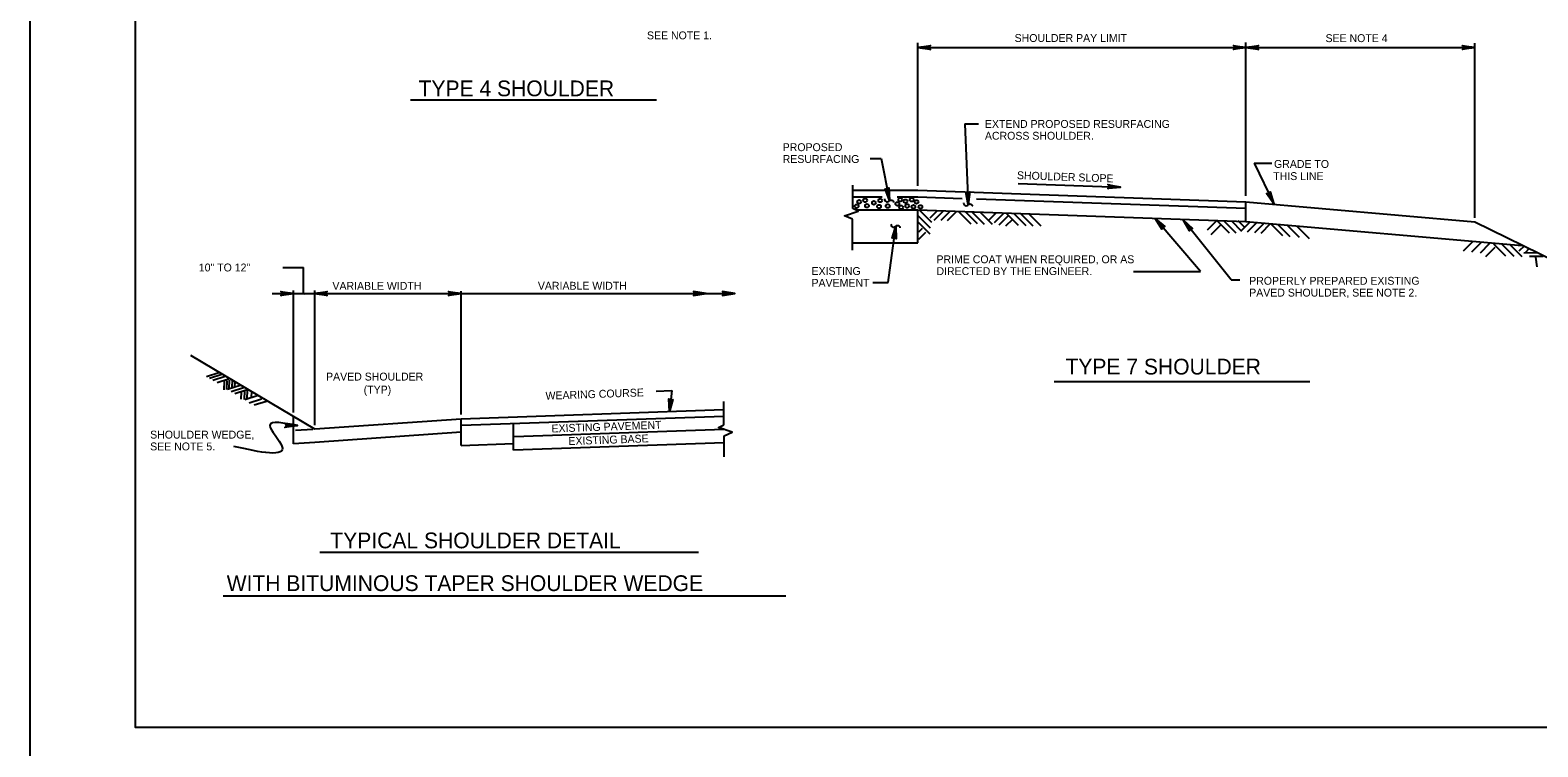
# Model space of a CAD drawing. Extents: x 638216 to 639962, y 297510 to 299292.
# Drawn here: x 638216 to 638790, y 298112 to 298385 of the extents above; entities that cross this region are included whole.
import ezdxf

# ---------------------------------------------------------------- set-up
doc = ezdxf.new("R2010")
doc.units = 0
for name, color, linetype in [('1', 7, 'Continuous'), ('2', 7, 'Continuous'), ('3', 7, 'Continuous'), ('PLT-BNDY', 7, 'Continuous')]:
    doc.layers.add(name, color=color, linetype=linetype)

msp = doc.modelspace()

# ---------------------------------------------------------------- linework, layer by layer
at = {"layer": '1'}
msp.add_lwpolyline([(639041.88, 298119.24), (639041.88, 298683.24), (638255.88, 298683.24), (638255.88, 298119.24), (639041.88, 298119.24), (639041.88, 298145.6), (638841.88, 298145.6), (638841.88, 298210.28), (639041.88, 298210.28), (639041.88, 298239.24), (638841.88, 298239.24), (638841.88, 298119.24), (638920.69, 298119.24), (638920.69, 298145.6), (638920.69, 298119.24), (638997.69, 298119.24), (638997.69, 298145.6), (638997.69, 298133.28), (639041.88, 298133.28)], dxfattribs=at)
msp.add_lwpolyline([(639041.88, 298119.24), (639041.88, 298683.24), (638255.88, 298683.24), (638255.88, 298119.24), (639041.88, 298119.24), (639041.88, 298145.6), (638841.88, 298145.6), (638841.88, 298210.28), (639041.88, 298210.28), (639041.88, 298239.24), (638841.88, 298239.24), (638841.88, 298119.24), (638920.69, 298119.24), (638920.69, 298145.6), (638920.69, 298119.24), (638997.69, 298119.24), (638997.69, 298145.6), (638997.69, 298133.28), (639041.88, 298133.28)], dxfattribs=at)
msp.add_spline([(638317.85, 298234.02), (638307.19, 298234.02), (638311.76, 298226.19), (638293.48, 298226.05)], degree=3, dxfattribs=at)
at = {"layer": '2'}
for p, q in [((638553.97, 298325.26), (638553.97, 298379.73)), ((638678.89, 298321.47), (638678.89, 298379.79)), ((638766.06, 298313.12), (638766.06, 298379.51)), ((638553.97, 298377.9), (638678.88, 298377.9)), ((638678.89, 298377.9), (638766.06, 298377.9)), ((638360.7, 298357.94), (638454.42, 298357.94)), ((638571.85, 298348.86), (638577.04, 298348.86)), ((638571.85, 298348.86), (638573.14, 298318.14)), ((638535.75, 298335.69), (638539.95, 298335.69)), ((638539.95, 298335.69), (638543.08, 298319.63)), ((638681.97, 298333.88), (638688.78, 298333.88)), ((638681.97, 298333.88), (638689.53, 298318.4)), ((638529.16, 298316.67), (638529.16, 298325.51)), ((638529.16, 298323.57), (638553.97, 298323.57)), ((638529.16, 298321.07), (638540.28, 298321.07)), ((638546, 298321.07), (638553.97, 298321.07)), ((638553.97, 298323.57), (638678.89, 298319.21)), ((638553.97, 298321.07), (638570.76, 298320.48)), ((638592.07, 298326.2), (638631.06, 298324.81)), ((638530.31, 298316.07), (638553.97, 298316.07)), ((638553.97, 298303.57), (638553.97, 298316.07)), ((638553.97, 298316.07), (638678.89, 298311.71)), ((638554.61, 298316.03), (638559.18, 298311.47)), ((638561.25, 298315.73), (638558.46, 298312.93)), ((638563.62, 298315.65), (638560.04, 298312.07)), ((638566.23, 298315.67), (638562.66, 298312.09)), ((638568.71, 298315.45), (638565.14, 298311.88)), ((638569.52, 298315.36), (638574.09, 298310.79)), ((638571.94, 298315.44), (638576.51, 298310.87)), ((638574.62, 298315.28), (638579.19, 298310.72)), ((638576.3, 298320.29), (638678.89, 298316.71)), ((638577.71, 298315.21), (638582.27, 298310.64)), ((638678.89, 298311.71), (638678.89, 298319.21)), ((638678.89, 298319.21), (638766.06, 298311.58)), ((638529.1, 298300.83), (638529.1, 298312.52)), ((638542.57, 298288.5), (638545.52, 298309.97)), ((638553.93, 298311.54), (638558.5, 298306.98)), ((638554.01, 298313.89), (638558.57, 298309.33)), ((638583.5, 298314.75), (638580.96, 298312.2)), ((638586.6, 298314.78), (638583.02, 298311.2)), ((638588.37, 298313.82), (638584.79, 298310.24)), ((638589.91, 298312.43), (638587.37, 298309.89)), ((638587.56, 298314.8), (638592.13, 298310.24)), ((638590.49, 298314.7), (638595.06, 298310.14)), ((638593.14, 298314.63), (638597.71, 298310.06)), ((638596.23, 298314.55), (638600.79, 298309.99)), ((638661.57, 298292.68), (638644.34, 298312.86)), ((638673.22, 298289.43), (638654.97, 298312.31)), ((638667.65, 298311.92), (638664.07, 298308.35)), ((638669.06, 298310.13), (638665.49, 298306.55)), ((638667.9, 298311.95), (638672.47, 298307.38)), ((638670.51, 298311.95), (638675.07, 298307.38)), ((638673.59, 298311.7), (638676.96, 298308.32)), ((638675.78, 298312.12), (638678.51, 298309.4)), ((638680.33, 298311.47), (638676.76, 298307.89)), ((638678.89, 298311.71), (638784.07, 298302.5)), ((638682.93, 298311.22), (638679.36, 298307.64)), ((638685.66, 298310.99), (638682.09, 298307.41)), ((638688.14, 298310.74), (638684.56, 298307.16)), ((638688.16, 298310.89), (638692.73, 298306.32)), ((638690.99, 298310.53), (638695.56, 298305.97)), ((638694.56, 298310.28), (638699.12, 298305.71)), ((638698.35, 298309.82), (638702.91, 298305.26)), ((638766.06, 298311.58), (638820.2, 298284.98)), ((638529.1, 298303.57), (638553.97, 298303.57)), ((638555.55, 298309.02), (638554.12, 298307.59)), ((638556.8, 298307.51), (638554.12, 298304.84)), ((638765.15, 298303.96), (638761.57, 298300.39)), ((638768.36, 298303.61), (638764.78, 298300.03)), ((638771.67, 298303.26), (638768.09, 298299.68)), ((638773.69, 298301.84), (638770.11, 298298.27)), ((638773.11, 298303.18), (638777.67, 298298.61)), ((638776.31, 298303.08), (638780.88, 298298.51)), ((638779.37, 298302.95), (638783.94, 298298.39)), ((638784.93, 298302.42), (638782.84, 298300.34)), ((638789.88, 298299.72), (638784.68, 298299.59)), ((638786.6, 298301.24), (638785.16, 298299.8)), ((638792, 298298.43), (638786.8, 298298.31)), ((638789.17, 298298.05), (638789.65, 298294.39)), ((638312.13, 298294.16), (638320.02, 298294.16)), ((638320.02, 298284.23), (638320.02, 298294.16)), ((638636.01, 298292.68), (638661.57, 298292.68)), ((638536.81, 298288.5), (638542.57, 298288.5)), ((638673.22, 298289.43), (638676.52, 298289.43)), ((638308.08, 298284.23), (638316.13, 298284.23)), ((638316.13, 298284.23), (638324.19, 298284.23)), ((638316.19, 298238.95), (638316.19, 298285.38)), ((638324.19, 298284.23), (638380, 298284.23)), ((638324.25, 298234.11), (638324.25, 298285.38)), ((638380, 298238.26), (638380, 298285.21)), ((638380, 298284.23), (638484.26, 298284.23)), ((638324.26, 298232.59), (638277.06, 298260.63)), ((638287.76, 298254.03), (638283.01, 298252.52)), ((638288.91, 298253.4), (638284.16, 298251.89)), ((638290.18, 298252.64), (638285.43, 298251.13)), ((638291.83, 298251.75), (638287.08, 298250.24)), ((638289.78, 298250.94), (638289.65, 298247.68)), ((638290.79, 298251.06), (638290.66, 298247.8)), ((638295.81, 298249.21), (638291.07, 298247.7)), ((638291.69, 298251.25), (638291.56, 298248)), ((638297.14, 298248.38), (638292.4, 298246.87)), ((638292.76, 298251.13), (638292.65, 298248.51)), ((638293.83, 298250.74), (638293.74, 298248.64)), ((638298.55, 298247.64), (638293.81, 298246.13)), ((638296.21, 298246.87), (638296.09, 298244.02)), ((638297.48, 298247.19), (638297.35, 298243.93)), ((638298.55, 298247.5), (638298.42, 298244.25)), ((638300.14, 298246.87), (638300.05, 298244.77)), ((638454.23, 298247.11), (638460.18, 298247.32)), ((638460.18, 298247.32), (638459.37, 298239.33)), ((638605.83, 298250.8), (638703.19, 298250.8)), ((638302.36, 298245.28), (638297.62, 298243.77)), ((638304.01, 298244.01), (638299.26, 298242.5)), ((638305.91, 298243.24), (638301.17, 298241.73)), ((638480.06, 298234.28), (638480.06, 298243.12)), ((638316.18, 298227.02), (638316.18, 298237.28)), ((638380.03, 298236.49), (638324.26, 298232.59)), ((638479.97, 298239.98), (638380.03, 298236.49)), ((638380.03, 298226.49), (638380.03, 298236.49)), ((638480.05, 298237.49), (638380.11, 298234)), ((638400.01, 298224.68), (638400.01, 298234.58)), ((638323.55, 298232.55), (638316.91, 298232.08)), ((638380.07, 298231.48), (638324.26, 298227.58)), ((638480.23, 298232.49), (638400.18, 298229.69)), ((638480.12, 298222.08), (638480.12, 298230.13)), ((638324.26, 298227.58), (638316.18, 298227.02)), ((638380.03, 298226.49), (638400.01, 298227.19)), ((638480.12, 298227.48), (638400.01, 298224.68)), ((638326.24, 298185.83), (638470.46, 298185.83)), ((638289.39, 298169.25), (638503.63, 298169.25))]:
    msp.add_line(p, q, dxfattribs=at)
for points in [[(638558.51, 298377.33), (638558.34, 298377.66), (638553.97, 298377.9), (638558.51, 298377.33), (638558.74, 298377.13), (638553.97, 298377.9), (638558.34, 298378.12), (638558.5, 298378.44), (638553.97, 298377.9), (638558.74, 298378.66), (638558.5, 298378.44)], [(638674.33, 298378.47), (638674.5, 298378.14), (638678.88, 298377.9), (638674.33, 298378.47), (638674.1, 298378.67), (638678.88, 298377.9), (638674.51, 298377.69), (638674.35, 298377.36), (638678.88, 298377.9), (638674.1, 298377.14), (638674.35, 298377.36)], [(638683.44, 298377.33), (638683.27, 298377.66), (638678.89, 298377.9), (638683.44, 298377.33), (638683.67, 298377.13), (638678.89, 298377.9), (638683.26, 298378.12), (638683.42, 298378.44), (638678.89, 298377.9), (638683.67, 298378.66), (638683.42, 298378.44)], [(638761.52, 298378.47), (638761.69, 298378.14), (638766.06, 298377.9), (638761.52, 298378.47), (638761.29, 298378.67), (638766.06, 298377.9), (638761.69, 298377.69), (638761.53, 298377.36), (638766.06, 298377.9), (638761.29, 298377.14), (638761.53, 298377.36)], [(638542.77, 298324.2), (638542.48, 298323.97), (638543.08, 298319.63), (638542.77, 298324.2), (638542.92, 298324.46), (638543.08, 298319.63), (638542.03, 298323.87), (638541.68, 298323.97), (638543.08, 298319.63), (638541.42, 298324.17), (638541.68, 298323.97)], [(638573.52, 298322.7), (638573.2, 298322.52), (638573.14, 298318.14), (638573.52, 298322.7), (638573.71, 298322.94), (638573.14, 298318.14), (638572.74, 298322.5), (638572.41, 298322.64), (638573.14, 298318.14), (638572.18, 298322.88), (638572.41, 298322.64)], [(638626.54, 298325.54), (638626.7, 298325.21), (638631.06, 298324.81), (638626.54, 298325.54), (638626.31, 298325.75), (638631.06, 298324.81), (638626.68, 298324.75), (638626.51, 298324.43), (638631.06, 298324.81), (638626.26, 298324.22), (638626.51, 298324.43)], [(638688.05, 298322.73), (638687.83, 298322.43), (638689.53, 298318.4), (638688.05, 298322.73), (638688.13, 298323.03), (638689.53, 298318.4), (638687.42, 298322.23), (638687.06, 298322.23), (638689.53, 298318.4), (638686.75, 298322.36), (638687.06, 298322.23)], [(638529.1, 298312.52), (638525.99, 298313.87), (638531.19, 298315.6), (638529.16, 298316.67)], [(638544.34, 298305.55), (638544.68, 298305.67), (638545.52, 298309.97), (638544.34, 298305.55), (638544.11, 298305.34), (638545.52, 298309.97), (638545.14, 298305.61), (638545.44, 298305.41), (638545.52, 298309.97), (638545.62, 298305.14), (638545.44, 298305.41)], [(638646.86, 298309.04), (638647, 298309.38), (638644.34, 298312.86), (638646.86, 298309.04), (638646.86, 298308.74), (638644.34, 298312.86), (638647.34, 298309.68), (638647.69, 298309.77), (638644.34, 298312.86), (638648.02, 298309.73), (638647.69, 298309.77)], [(638657.35, 298308.4), (638657.5, 298308.74), (638654.97, 298312.31), (638657.35, 298308.4), (638657.34, 298308.1), (638654.97, 298312.31), (638657.86, 298309.03), (638658.21, 298309.11), (638654.97, 298312.31), (638658.54, 298309.05), (638658.21, 298309.11)], [(638311.59, 298284.8), (638311.76, 298284.47), (638316.13, 298284.23), (638311.59, 298284.8), (638311.36, 298285), (638316.13, 298284.23), (638311.76, 298284.02), (638311.6, 298283.69), (638316.13, 298284.23), (638311.36, 298283.47), (638311.6, 298283.69)], [(638328.73, 298283.66), (638328.56, 298283.99), (638324.19, 298284.23), (638328.73, 298283.66), (638328.96, 298283.46), (638324.19, 298284.23), (638328.56, 298284.45), (638328.71, 298284.77), (638324.19, 298284.23), (638328.96, 298284.99), (638328.71, 298284.77)], [(638375.46, 298284.8), (638375.63, 298284.47), (638380, 298284.23), (638375.46, 298284.8), (638375.23, 298285), (638380, 298284.23), (638375.63, 298284.02), (638375.47, 298283.69), (638380, 298284.23), (638375.23, 298283.47), (638375.47, 298283.69)], [(638468.73, 298283.66), (638468.9, 298283.99), (638473.27, 298284.23), (638468.73, 298283.66), (638468.5, 298283.46), (638473.27, 298284.23), (638468.9, 298284.45), (638468.74, 298284.77), (638473.27, 298284.23), (638468.5, 298284.99), (638468.74, 298284.77)], [(638479.72, 298283.66), (638479.89, 298283.99), (638484.26, 298284.23), (638479.72, 298283.66), (638479.48, 298283.46), (638484.26, 298284.23), (638479.89, 298284.45), (638479.73, 298284.77), (638484.26, 298284.23), (638479.48, 298284.99), (638479.73, 298284.77)], [(638460.39, 298243.79), (638460.05, 298243.65), (638459.37, 298239.33), (638460.39, 298243.79), (638460.62, 298244), (638459.37, 298239.33), (638459.6, 298243.7), (638459.29, 298243.89), (638459.37, 298239.33), (638459.1, 298244.16), (638459.29, 298243.89)], [(638313.12, 298234.59), (638313.29, 298234.26), (638317.66, 298234.02), (638313.12, 298234.59), (638312.89, 298234.79), (638317.66, 298234.02), (638313.29, 298233.81), (638313.13, 298233.48), (638317.66, 298234.02), (638312.89, 298233.26), (638313.13, 298233.48)], [(638480.12, 298230.13), (638483.23, 298231.48), (638478.03, 298233.22), (638480.06, 298234.28)]]:
    msp.add_lwpolyline(points, dxfattribs=at)
for centre in [(638547.22, 298319.99), (638551.58, 298319.99), (638530.63, 298317.49), (638531.58, 298319.16), (638533.87, 298319.75), (638534.56, 298317.67), (638537.19, 298318.8), (638539.14, 298317.36), (638539.6, 298319.71), (638542.45, 298317.57), (638546.12, 298318.39), (638547.58, 298317.07), (638549.23, 298319.41), (638549.89, 298317.6), (638552.24, 298317.26), (638553.45, 298319.15), (638554.92, 298317.23)]:
    msp.add_circle(centre, 0.712, dxfattribs=at)
for points in [[(638541.2, 298320.3), (638541.35, 298319.85), (638541.93, 298319.23), (638542.65, 298319.28), (638543.08, 298319.63), (638543.68, 298319.85), (638544.35, 298319.63), (638544.53, 298319.4), (638544.65, 298318.95)], [(638571.26, 298318.82), (638571.41, 298318.37), (638571.99, 298317.74), (638572.71, 298317.79), (638573.14, 298318.14), (638573.74, 298318.37), (638574.41, 298318.14), (638574.59, 298317.92), (638574.71, 298317.47)], [(638543.64, 298310.64), (638543.79, 298310.19), (638544.37, 298309.57), (638545.09, 298309.62), (638545.52, 298309.97), (638546.12, 298310.19), (638546.79, 298309.97), (638546.97, 298309.74), (638547.09, 298309.29)]]:
    msp.add_spline(points, degree=3, dxfattribs=at)
at = {"layer": 'PLT-BNDY'}
msp.add_lwpolyline([(638215.88, 298698.24), (639056.88, 298698.24), (639056.88, 298104.24), (638215.88, 298104.24)], close=True, dxfattribs=at)

# ---------------------------------------------------------------- texts
at = {"layer": '2'}
msp.add_text('.', height=3, rotation=350, dxfattribs=at).set_placement((638319.72, 298283.88))
at = {"layer": '3'}
for s, height, p in [('SEE NOTE 1.', 3, (638450.78, 298381.02)), ('SHOULDER PAY LIMIT', 3, (638590.78, 298380.03)), ('SEE NOTE 4', 3, (638709.19, 298379.97)), ('TYPE 4 SHOULDER', 6, (638363.8, 298359.36)), ('EXTEND PROPOSED RESURFACING', 3, (638579.47, 298347.32)), ('ACROSS SHOULDER.', 3, (638579.47, 298342.82)), ('PROPOSED', 3, (638502.46, 298338.47)), ('RESURFACING', 3, (638502.46, 298333.97)), ('GRADE TO ', 3, (638689.57, 298332.09)), ('THIS LINE', 3, (638689.27, 298327.46)), ('PRIME COAT WHEN REQUIRED, OR AS', 3, (638561.02, 298295.8)), ('10" TO 12"', 3, (638280.11, 298292.68)), ('EXISTING', 3, (638513.44, 298291.33)), ('DIRECTED BY THE ENGINEER.', 3, (638561.02, 298291.3)), ('VARIABLE WIDTH', 3, (638331, 298285.69)), ('VARIABLE WIDTH', 3, (638409.23, 298285.73)), ('PAVEMENT', 3, (638513.44, 298286.83)), ('PROPERLY PREPARED EXISTING', 3, (638680.11, 298287.62)), ('PAVED SHOULDER, SEE NOTE 2.', 3, (638680.11, 298283.12)), ('TYPE 7 SHOULDER', 6, (638610.14, 298253.46)), ('PAVED SHOULDER', 3, (638328.57, 298251.16)), ('(TYP)', 3, (638342.9, 298246.2)), ('SHOULDER WEDGE,', 3, (638261.59, 298229.07)), ('SEE NOTE 5.', 3, (638261.59, 298224.57)), ('TYPICAL SHOULDER DETAIL', 6, (638330.2, 298187.3)), ('WITH BITUMINOUS TAPER SHOULDER WEDGE ', 6, (638290.73, 298171.03))]:
    msp.add_text(s, height=height, dxfattribs=at).set_placement(p)
for s, rotation, p in [('SHOULDER SLOPE', 357.99987, (638591.63, 298327.83)), ('WEARING COURSE', 2.00003, (638412.2, 298243.85)), ('EXISTING PAVEMENT', 2.00009, (638414.48, 298231.37)), ('EXISTING BASE', 2.00004, (638420.91, 298226.59))]:
    msp.add_text(s, height=3, rotation=rotation, dxfattribs=at).set_placement(p)

doc.saveas('drawing.dxf')
